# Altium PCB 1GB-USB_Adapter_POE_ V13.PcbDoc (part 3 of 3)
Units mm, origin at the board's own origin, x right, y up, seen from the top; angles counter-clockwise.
Board outline 92 x 80 mm, 4 copper layers (Top Layer, Signal Layer 2, Signal Layer 3, Bottom Layer), stack 1.57 mm thick; 189 components, 102 nets, 551 pads, 429 vias.
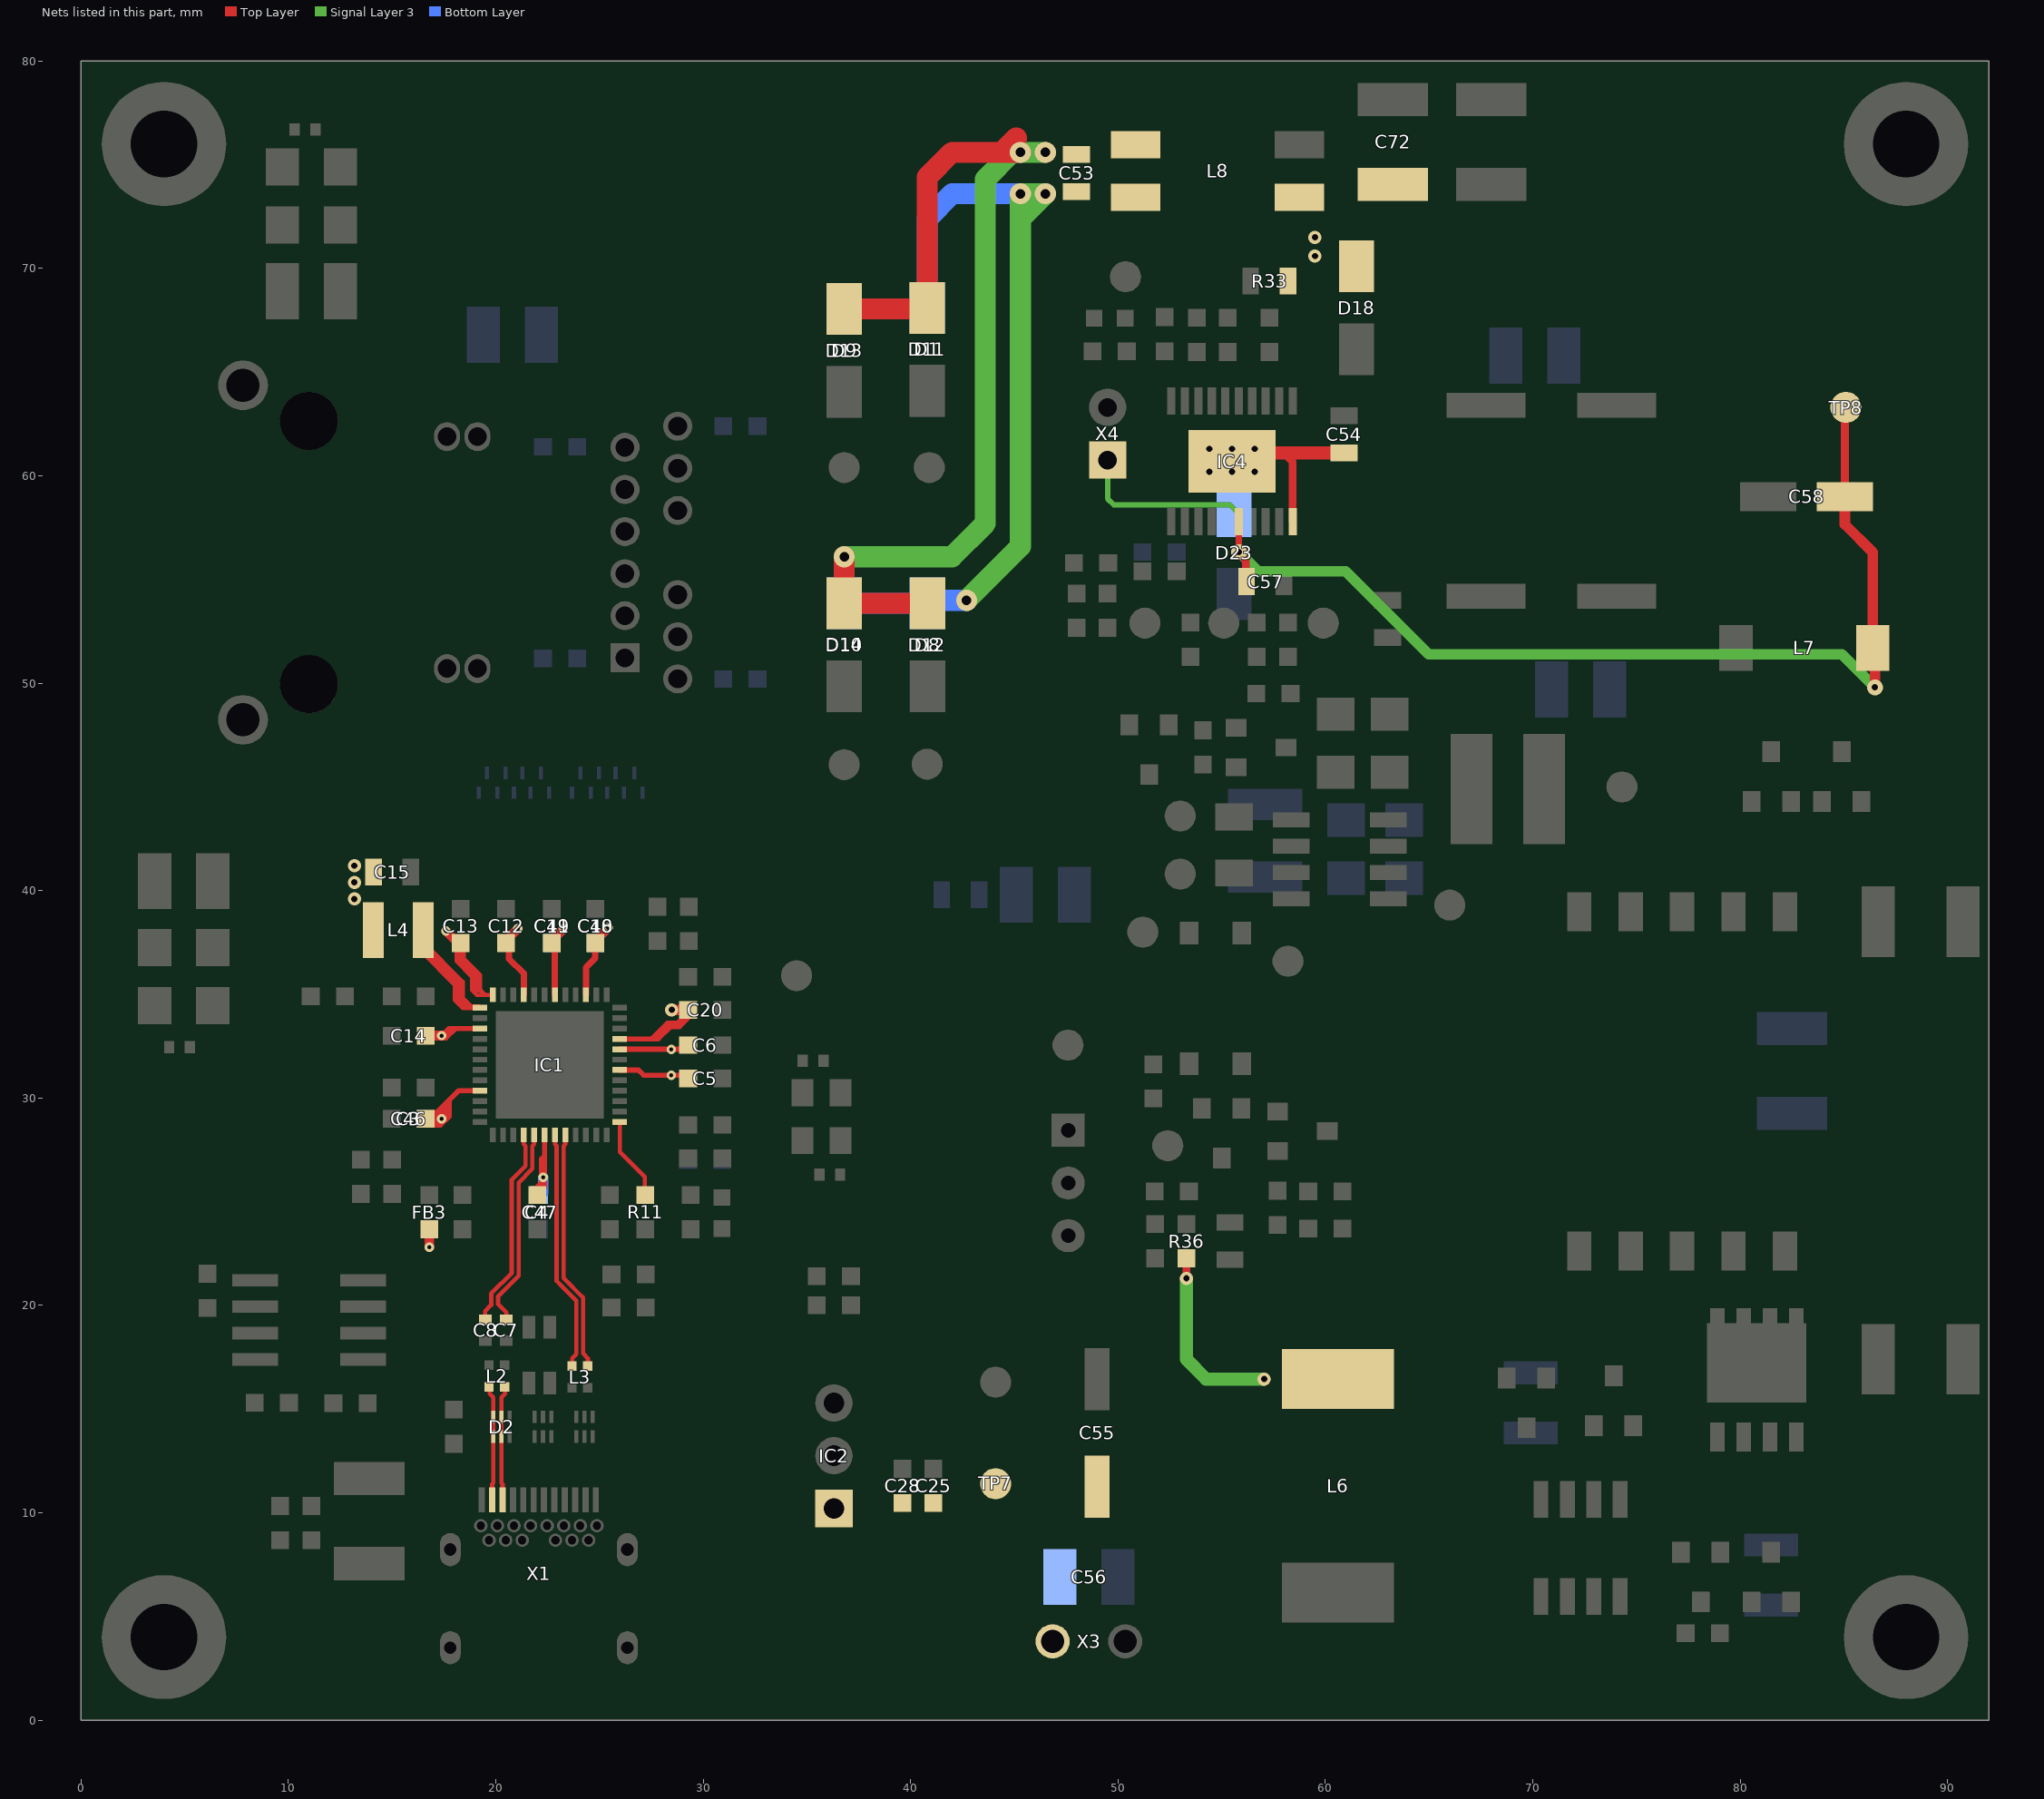
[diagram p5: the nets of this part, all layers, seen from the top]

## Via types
v1: diameter 0.635, hole 0.3, Top Layer to Bottom Layer, tented both sides, 260 vias
v2: diameter 0.45, hole 0.2, Top Layer to Bottom Layer, tented both sides, 80 vias
v3: diameter 1.016, hole 0.457, Top Layer to Bottom Layer, tented both sides, 55 vias
v4: diameter 1.016, hole 0.508, Top Layer to Bottom Layer, 32 vias
v5: diameter 0.762, hole 0.3, Top Layer to Bottom Layer, tented both sides, 2 vias

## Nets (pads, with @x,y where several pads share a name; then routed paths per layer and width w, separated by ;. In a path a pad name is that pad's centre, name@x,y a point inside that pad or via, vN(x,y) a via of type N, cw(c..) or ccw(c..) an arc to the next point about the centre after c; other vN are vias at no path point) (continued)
USB3RX_N: IC1.32 L3.3 | length 12.3
  Top Layer w0.206: IC1.32@23.35,28.225 23.35,27.772 23.266,27.689 23.266,21.314 23.48,21.1 ; L3.3@24.436,17.125 24.436,17.453 24.211,17.678 24.211,20.369 23.98,20.6 ; 23.48,21.1 23.98,20.6 ; 23.48,21.1 23.98,20.6
USB3RX_P: IC1.31 L3.2 | length 12.3
  Top Layer w0.206: IC1.31@22.85,28.225 22.85,27.772 22.934,27.688 22.934,21.176 23.147,20.962 ; L3.2@23.686,17.125 23.686,17.453 23.878,17.645 23.878,20.232 23.647,20.462 ; 23.147,20.962 23.647,20.462 ; 23.147,20.962 23.647,20.462
USB3TX1_N: D2.2 D2.5 L2.4 X1.A3 | length 5.5
  Top Layer w0.206: X1.A3@20.325,10.68 20.325,11.383 20.275,11.433 20.275,13.725 20.275,14.675 20.275,15.572 20.45,15.747 L2.4@20.45,16.075
USB3TX1_P: D2.1 D2.6 L2.1 X1.A2 | length 5.5
  Top Layer w0.206: L2.1@19.7,16.075 19.7,15.747 19.875,15.572 19.875,14.675 19.875,13.725 19.875,11.433 19.825,11.383 X1.A2@19.825,10.68
USB3TX_N: C7.2 IC1.29 | length 9.8
  Top Layer w0.206: C7.2@20.51,19.3 20.51,19.653 20.11,20.053 20.11,20.436 21.1,21.426 21.1,25.92 21.766,26.586 21.766,27.689 21.85,27.772 IC1.29@21.85,28.225
USB3TX_P: C8.2 IC1.28 | length 9.8
  Top Layer w0.206: C8.2@19.48,19.3 19.48,19.723 19.777,20.02 19.777,20.574 20.767,21.564 20.767,26.058 21.434,26.724 21.434,27.689 21.35,27.772 IC1.28@21.35,28.225
USBRBIAS: IC1.37 R11.1 | length 4
  Top Layer w0.203: IC1.37@25.975,28.85 25.975,27.405 27.18,26.2 R11.1@27.18,25.325
VC: C57.1 C58.1 IC4.6 L7.1 TP8.1 X4.1 | length 60.7
  Top Layer w0.305: IC4.6@55.825,57.8 v5(55.83,56.327)
  Top Layer w0.381: v5(55.83,56.327) 56.16,55.895 C57.1@56.16,54.879 ; C58.1@85.05,59 TP8.1@85.05,63.25
  Top Layer w0.508: C58.1@85.05,59 85.05,57.658 86.4,56.308 L7.1@86.4,51.7 ; v5(86.5,49.8) L7.1@86.5,51.6
  Signal Layer 3 w0.254: X4.1@49.5,60.76 49.5,58.9 49.8,58.6 55.4,58.6 55.83,58.17 v5(55.83,56.327)
  Signal Layer 3 w0.508: v5(55.83,56.327) 56.757,55.4 60.977,55.4 64.977,51.4 84.9,51.4 v5(86.5,49.8)
VDD12: C3.1 C4.1 C5.1 C6.1 C14.1 C15.2 C46.1 C47.1 FB3.2 IC1.15 IC1.21 IC1.30 IC1.42 IC1.44 L4.2 | length 24.9
  Top Layer w0.25: C14.1@16.586,33.005 16.713,33.132 17.538,33.132 17.756,33.35 18.046,33.35 ; C3.1@16.606,29 16.906,28.7 17.332,28.7 17.756,29.124 17.756,29.45 17.756,29.9 ; C14.1@16.691,32.9 17.386,32.9 17.596,32.9 18.046,33.35 ; C3.1@16.713,29.3 17.156,29.3 17.443,29.587 17.756,29.9 ; IC1.21@19.225,30.35 18.206,30.35 17.756,29.9 ; IC1.15@19.225,33.35 18.046,33.35 ; IC1.30@22.35,28.225 22.35,27.197 ; IC1.42@25.975,31.35 26.88,31.35 27.13,31.1 28.955,31.1 v2(28.46,31.1) ; IC1.44@25.975,32.35 C6.1@29.205,32.35 ; 22.35,27.197 22.35,26.172 22.35,25.695 21.98,25.325 21.98,25.68 22.2,25.9 22.2,26.172 22.2,27.047 22.35,27.197
  Top Layer w0.45: v2(16.8,22.8) FB3.2@16.8,23.674
  Top Layer w0.508: C3.1@16.606,29 17.13,29 17.293,29.163 17.58,29.45
  Bottom Layer w0.5: C47.1@22.28,25.425 v2(22.28,26.172)
  Bottom Layer w0.508: C46.1@16.605,29 v2(17.38,29)
  other v1: 13.18,39.6 13.18,40.4 13.18,41.2
  other v2: 28.46,32.345 17.386,33.005
VDD12_SW_OUT: IC1.13 L4.1 | length 13.7
  Top Layer w0.25: L4.1@16.452,38.085 L4.1@16.452,37.523 ; IC1.13@19.18,34.4 18.8,34.4 18.38,34.82 18.38,35.595 L4.1@16.452,37.523 ; IC1.13@19.225,34.35 18.8,34.35 18.58,34.35 ; L4.1@16.452,37.328 L4.1@16.452,37.523 ; L4.1@16.452,37.328 16.452,37.064 18.046,35.47 18.046,34.734 18.105,34.675 18.43,34.35 18.58,34.35 ; L4.1@16.452,37.328 18.18,35.6 18.18,34.75 18.505,34.425 18.58,34.35
VDD25: C10.1 C11.1 C12.1 C13.1 C20.1 C48.1 C49.1 IC1.3 IC1.6 IC1.9 IC1.12 IC1.45 | length 29.7
  Top Layer w0.2: C13.1@18.1,37.369 18.1,36.595 18.85,35.845 18.85,35.205 19.08,34.975 19.48,34.975 ; C13.1@18.175,37.369 C13.1@18.28,37.474 ; C13.1@18.45,37.304 18.45,36.73 19.25,35.93 19.25,35.205 19.48,34.975 ; IC1.12@19.85,34.975 19.48,34.975
  Top Layer w0.25: C13.1@18.28,37.474 18.28,37.369 18.28,36.64 19.032,35.888 19.032,35.3 19.127,35.205 19.25,35.205 ; IC1.45@25.975,32.85 27.53,32.85 ; v1(28.48,34.25) v1@28.505,34.225 ; v1@28.779,34.224 28.805,34.25 ; C20.1@29.279,34.25 29.279,34.116 28.763,33.6 28.28,33.6 27.53,32.85 ; C20.1@29.354,33.949 28.855,33.45 28.43,33.45 27.83,32.85 27.53,32.85
  Top Layer w0.305: C12.1@20.48,37.474 20.637,37.318 20.637,36.713 21.35,36 IC1.9@21.35,34.975 ; C11.1@22.68,37.474 22.85,37.305 IC1.6@22.85,34.975 ; IC1.3@24.35,34.975 24.35,36.3 24.78,36.73 C10.1@24.78,37.474
  Top Layer w0.45: v2(17.593,38.056) C13.1@18.175,37.474 ; C13.1@18.28,37.474 C13.1@18.45,37.304 ; C12.1@20.48,37.58 v2(21.062,38.162) ; C11.1@22.68,37.58 v2(23.262,38.162) ; C10.1@24.83,37.63 v2(25.412,38.212)
  Top Layer w0.508: v1(28.48,34.25) 28.805,34.25 29.255,34.25 C20.1@29.279,34.25
  Bottom Layer w0.45: C49.1@22.68,37.58 v2(23.262,38.162) ; C48.1@24.78,37.58 v2(25.412,38.212)
VDD_POE: C53.2 D1.2 D8.2 D9.2 D10.2 L8.2 | length 50.1
  Top Layer w1.016: D10.2@36.8,53.85 D8.2@40.82,53.85 D8.2@40.9,53.93 ; D10.2@36.8,53.93 v3(36.8,56.1) ; D9.2@36.8,68.05 40.75,68.05 D1.2@40.8,68.1 40.8,74.4 42,75.6 44.4,75.6 ; 45.1,76.3 44.4,75.6 ; v3(45.3,75.6) 44.4,75.6
  Signal Layer 3 w1.016: v3(36.8,56.1) 42,56.1 43.6,57.7 43.6,74.3 44.9,75.6 v3(45.3,75.6) v3(46.5,75.6)
VOUT: C25.2 C28.1 C55.1 C56.1 IC2.1 L6.2 R36.2 TP7.1 X3.1 | length 9
  Top Layer w0.381: v1(53.3,21.3) R36.2@53.3,22.274
  Signal Layer 3 w0.635: v1(53.3,21.3) 53.3,17.4 54.25,16.45 v1(57.049,16.45)
VSS: C54.2 C72.2 D18.1 D23.1 IC4.10 IC4.21 L8.4 R33.1 | length 8.5
  Top Layer w0.381: 58,61.1 58.425,60.675 IC4.10@58.425,57.8
  Top Layer w0.635: IC4.21@55.9,61.1 58,61.1 C54.2@60.9,61.1
  other v1: 54.4,60.2 55.5,60.2 56.6,60.2 54.4,61.3 55.5,61.3 56.6,61.3 59.5,70.6 59.5,71.5
VSS_POE: C53.1 D11.1 D12.1 D13.1 D14.1 L8.1 | length 44.1
  Signal Layer 3 w1.016: v3(42.7,54) 45.3,56.6 45.3,72.4 ; 45.3,72.4 v3(46.5,73.6) v3(45.3,73.6) 45.3,72.4
  Bottom Layer w1.016: D14.1@36.8,53.85 D12.1@40.8,53.85 40.95,54 v3(42.7,54) ; D13.1@36.8,68.05 40.75,68.05 D11.1@40.8,68.1 40.8,72.4 42,73.6 v3(45.3,73.6) v3(46.5,73.6)
pads on no net: D2.4 D3.4 D4.4 D6.2 D6.4 D6.7 D6.8 D7.2 D7.4 D7.7 D7.8 D15.2 D16.2 D17.2 D19.2 D20.2 D21.2 D22.2 IC3.7 IC4.14 IC4.17 T2.3 T2.8 X1.A4 X1.A8 X1.A9 X1.A10 X1.A11 X1.B2 X1.B3 X1.B4 X1.B5 X1.B8 X1.B9 X2.MH1 X2.MH2

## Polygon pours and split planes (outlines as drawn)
AGND on Top Layer "NONET_L03_P-001" (solid, remove dead copper, pour order 58): 65.2,32.5 61.7,36 46.6,36 45.5,37.1 45.5,44.6 45.5,76.7 79.4,76.7 88.5,67.6 88.5,33.2 87.8,32.5
GND on Top Layer "NONET_L03_P-001" (solid, remove dead copper, pour order 56): 42.409,43.091 42.9,42.6 42.9,35.8 45.25,33.45 60.15,33.45 63.6,30 87.8,30 88.5,29.3 88.5,10.15 86.375,8.025 86.325,8.025 84,5.65 84,3.1 83.2,2.3 80.6,2.3 43.8,2.3 41.1,5 30,5 29.5,5.5 29.5,9.5 29,10 7,10 5,12 5,32.694 5.497,33.191 5.497,41.308 11.8,47.61 11.8,74 11.8,75.5 10.95,76.35 10.95,77.1 21.8,77.1 22.1,76.8 22.1,48.4 22.71,47.79 32.71,47.79 33.169,47.331 33.169,43.612 33.69,43.091
NetD17_3 on Top Layer "NONET_L-01_P-001" (solid, remove dead copper, pour order 36): 71.45,23.7 71.45,15.65 71.8,15.3 84.3,15.3 84.6,15.6 84.6,19.8 84.3,20.1 75.9,20.1 75.6,20.4 75.6,23.7 75.425,23.874 71.625,23.874
VOUT on Top Layer "NONET_L-01_P-001" (solid, remove dead copper, pour order 34): 45.515,2.9 45.2,3.215 45.2,8.1 44.821,8.479 35.02,8.479 34.67,8.829 34.67,10.99 35.013,11.333 42.133,11.333 44.3,13.5 51.6,13.5 56.65,18.55 64.05,18.55 64.3,18.3 64.3,14.284 64,13.984 56.759,13.984 48.4,5.625 48.4,3.1 48.2,2.9
NetC2_2 on Top Layer "NONET_L-01_P-001" (solid, remove dead copper, pour order 28): 59.55,46.7 59.4,46.55 59.4,44.716 59.516,44.6 61.75,44.6 61.95,44.4 61.95,38 62.05,37.9 66.846,37.9 67.1,38.154 67.1,40.081 66.993,40.188 64.6,40.188 64.3,40.488 64.3,46.5 64.1,46.7
NetR34_2 on Top Layer "Top Layer, Top-RCS" (solid, remove dead copper, pour order 26): 59.507,40.4 57.378,40.4 56.7,39.722 52.103,39.722 51.95,39.875 51.95,41.85 52.134,42.034 56.966,42.034 57.125,42.192 57.125,43.989 59.516,43.989 59.528,43.976
NetC45_1 on Top Layer "NONET_L-01_P-001" (solid, remove dead copper, pour order 22): 73.2,37.9 73.2,51.4 72.9,51.7 70,51.7 69.4,51.1 69.4,38.2 69.7,37.9
VSS on Top Layer "NONET_L-01_P-001" (solid, remove dead copper, pour order 16): 56.21,73.2 56.209,74.415 56.615,74.82 61.12,74.82 65.28,74.82 65.6,74.5 65.6,69.759 63.941,68.1 60.395,68.1 60.195,68.3 57.4,68.3 57.2,68.5 57.2,70.17 57.07,70.3 56.3,70.3 56.21,70.391
NetC34_1 on Top Layer "NONET_L-01_P-001" (solid, remove dead copper, pour order 14): 65.3,68.7 66.1,69.5 66.1,74.9 65.644,75.356 56.907,75.356 56.907,76.7 69.5,76.7 70.1,76.1 70.1,53.5 68.1,51.5 68.1,41.8 67.9,41.6 65.7,41.6 65.3,42 65.3,52.7 64.9,53.1 62.325,53.1 62.075,53.35 62.075,61.875 61.95,62 59.81,62 59.65,62.16 59.65,67.651 64.251,67.651
SHIELD on Top Layer "NONET_L-01_P-001" (solid, remove dead copper, pour order 10): 17.555,9.1 18.54,8.115 18.54,6.594 18.775,6.359 25.313,6.359 25.61,6.656 25.61,8.235 26.475,9.1 27.651,9.1 28.076,8.675 28.076,4.007 28.589,3.574 40.526,3.574 42.7,1.4 42.7,0 0,0 0,80 92,80 92,0 84.4,0 84.4,1.5 90,7.1 90,68.86 80.66,78.2 11.5,78.2 10.54,77.24 10.54,48.151 4.4,42.011 4.4,11.31 6.61,9.1
3V3_Board on Top Layer "NONET_L-01_P-001" (solid, remove dead copper, pour order 8): 33.1,14.5 33.4,14.2 37.734,14.2 37.979,14.445 37.979,18.646 37.675,18.95 36.354,18.95 36.104,19.2 36.104,21.969 35.973,22.1 33.3,22.1 33.1,21.9
GND on Top Layer "GND_OSC" (solid, remove dead copper, pour order 6): 33.303,32.525 33.603,32.825 38.003,32.825 38.303,32.525 38.303,25.655 37.979,25.331 33.548,25.331 33.303,25.575
3V3_Board on Top Layer "3V3_BOARD_L01_P004" (hatched Horizontal grid 0.203 track 0.203, remove dead copper, pour order 4): 28.445,36.08 29.025,36.08 29.025,35.62 28.955,35.55 28.63,35.55 27.78,34.7 27.78,33.7 27.43,33.35 26.763,33.35 27.28,33.867 27.28,34.915
3V3_Board on Top Layer "3V3_BOARD_L01_P002" (hatched Horizontal grid 0.203 track 0.203, remove dead copper, pour order 2): 28.28,29 27.43,29.85 27.08,29.85 27.525,29.405 27.525,28.555 27.68,28.4 28.955,28.4 29.217,28.662 29.217,29
3V3_Board on Top Layer "3V3_BOARD_L01_P000" (hatched Horizontal grid 0.203 track 0.203, remove dead copper, pour order 0): 27.68,27.4 28.955,27.4 28.955,26.8 27.48,26.8 26.856,27.424 26.856,28 27.08,28
GND on Bottom Layer "NONET_L03_P-001" (solid, remove dead copper, pour order 72): 42.9,41.275 42.725,41.1 42,41.1 41.75,40.85 41.75,38.85 42,38.6 42.7,38.6 42.9,38.4 42.9,36.804 42.9,35.8 45.25,33.45 60.15,33.45 63.6,30 87.8,30 88.5,29.3 88.5,10.15 86.375,8.025 86.325,8.025 84,5.65 84,3.1 83.2,2.3 80.6,2.3 43.8,2.3 41.1,5 30,5 29.5,5.5 29.5,9.5 29,10 7,10 5.497,11.503 5.497,33.191 5.497,41.308 11.804,47.614 11.804,63.404 12.239,63.839 21.661,63.839 22.1,63.4 22.1,48.4 22.71,47.79 32.71,47.79 33.169,47.331 33.169,43.612 33.69,43.091 42.41,43.091 42.9,42.6
AGND on Bottom Layer "NONET_L03_P-001" (solid, remove dead copper, pour order 64): 45.497,54.9 46.5,55.903 46.5,71.6 48,73.1 48,75.175 48.625,75.8 80.297,75.8 88.497,67.6 88.497,33.2 87.797,32.5 65.197,32.5 61.697,36 47.3,36 46.546,36.754 46.546,41.8 46.246,42.1 45.497,42.849 45.497,43.003 45.497,44.6
SHIELD on Bottom Layer "NONET_L-01_P-001" (solid, remove dead copper, pour order 48): 10.5,64.2 11.3,65 19.854,65 20.454,65.6 20.454,77.454 21.2,78.2 80.66,78.2 90,68.86 90,7.1 84.4,1.5 84.4,0 92,0 92,80 0,80 0,0 42.7,0 42.7,1.4 40.526,3.574 28.589,3.574 28.076,4.007 28.076,8.675 27.651,9.1 26.475,9.1 25.61,8.235 25.61,6.656 25.313,6.359 18.775,6.359 18.54,6.594 18.54,8.115 17.555,9.1 6.61,9.1 4.4,11.31 4.4,42.011 10.5,48.111
NetD17_3 on Bottom Layer "NONET_L-01_P-001" (solid, remove dead copper, pour order 38): 68.575,15.3 68.275,15.6 68.275,19.875 68.5,20.1 71.225,20.1 71.45,20.4 71.45,23.7 71.625,23.874 75.425,23.874 75.6,23.7 75.6,20.4 75.9,20.1 84.3,20.1 84.6,19.8 84.6,15.6 84.3,15.3
NetC45_1 on Bottom Layer "NONET_L-01_P-001" (solid, remove dead copper, pour order 24): 73.2,37.9 73.2,51.4 72.9,51.7 70,51.7 69.4,51.1 69.4,38.2 69.7,37.9
VSS on Bottom Layer "Bottom Layer, Bottom-VSS" (solid, remove dead copper, pour order 18): 60.222,71.878 60.1,72 57.7,72 57.555,71.855 57.555,64.586 57.461,64.492 53.631,64.492 53.618,64.479 53.618,57.621 53.631,57.608 60.221,57.608 60.374,57.765 60.222,68.556
GND on Signal Layer 2 "NONET_L03_P-001" (solid, remove dead copper, pour order 66): 42.9,37.167 42.9,35.8 45.275,33.48 45.31,33.45 60.15,33.45 63.6,30 87.8,30 88.5,29.3 88.5,10.15 86.375,8.025 86.325,8.025 84,5.65 84,3.1 83.2,2.3 80.6,2.3 43.8,2.3 41.1,5 30,5 29.5,5.5 29.5,9.5 29,10 26.865,10 24.565,7.7 19.643,7.7 17.343,10 15.88,10 7,10 5.497,11.503 5.497,33.191 5.497,41.308 11.8,47.61 11.8,72.7 11.8,76.796 12.104,77.1 21.8,77.1 22.1,76.8 22.1,48.4 22.71,47.79 32.71,47.79 33.169,47.331 33.169,43.612 33.69,43.091 42.409,43.091 42.9,42.6
AGND on Signal Layer 2 "NONET_L03_P-001" (solid, remove dead copper, pour order 60): 45.5,54.9 46.5,55.9 46.5,71.6 48,73.1 48,75.175 48.625,75.8 80.3,75.8 88.5,67.6 88.5,33.2 87.8,32.5 65.2,32.5 61.7,36 46.6,36 45.5,37.1 45.5,44.6
SHIELD on Signal Layer 2 "NONET_L-01_P-001" (solid, remove dead copper, pour order 44): 28.076,8.689 27.7,9.065 27.395,9.065 25.23,6.9 18.9,6.9 16.7,9.1 6.61,9.1 4.4,11.31 4.4,42.011 10.54,48.151 10.54,77.24 11.5,78.2 80.66,78.2 90,68.86 90,7.1 84.4,1.5 84.4,0 92,0 92,80 0,80 0,0 42.7,0 42.7,1.4 40.526,3.574 28.589,3.574 28.076,4.007
NetC52_2 on Signal Layer 2 "NONET_L03_P-001" (solid, remove dead copper, pour order 40): 57,6.9 57.2,7.1 80.825,7.1 85,11.275 85,24.8 85.1,24.9 87.6,24.9 87.7,24.8 87.7,9.9 83.2,5.4 83.2,3.495 82.505,2.8 57.23,2.8 57,3.03
GND on Signal Layer 3 "NONET_L03_P-001" (solid, remove dead copper, pour order 70): 42.9,36.965 42.9,35.798 45.248,33.45 46.05,33.45 60.15,33.45 63.6,30 87.8,30 88.5,29.3 88.5,10.15 86.375,8.025 86.325,8.025 84,5.65 84,3.1 83.2,2.3 80.6,2.3 43.8,2.3 41.1,5 30,5 29.5,5.5 29.5,9.5 29,10 7,10 5.497,11.503 5.497,33.191 5.497,41.308 11.804,47.614 11.804,76.8 12.104,77.1 13,77.1 21.8,77.1 22.1,76.8 22.1,48.4 22.71,47.79 32.71,47.79 33.169,47.331 33.169,43.612 33.69,43.091 42.409,43.091 42.9,42.6
AGND on Signal Layer 3 "NONET_L03_P-001" (solid, remove dead copper, pour order 62): 45.5,54.9 46.5,55.9 46.5,71.6 48,73.1 48,75.175 48.625,75.8 80.3,75.8 88.5,67.6 88.5,33.2 87.8,32.5 65.2,32.5 61.7,36 46.6,36 45.5,37.1 45.5,44.6
VDD12 on Signal Layer 3 "VDD12_L03_P054" (solid, remove dead copper, pour order 54): 16.446,35.139 16.446,32.7 16.573,32.573 17.97,32.573 18.097,32.446 18.097,29.601 17.894,29.398 15.766,29.398 15.608,29.256 15.608,22.489 15.785,22.312 16.979,22.312 17.132,22.464 17.132,25.537 17.259,25.664 28.562,25.664 28.714,25.817 28.714,32.522 28.587,32.649 26.901,32.649 26.784,32.767 26.784,36.459 26.53,36.713 17.309,36.713 17.055,36.967 17.055,42.507 16.855,42.708 12.585,42.708 12.382,42.505 12.382,35.596 12.56,35.418 16.166,35.418
3V3_Board on Signal Layer 3 "3V3_BOARD_L03_P052" (solid, remove dead copper, pour order 52): 31.051,22.349 31.4,22 34.6,22 34.8,21.8 34.8,20.2 34.581,19.981 23.719,19.981 23.5,20.2 23.507,22.921 23.355,23.074 19.265,23.074 19.164,22.972 19.164,20.534 18.935,20.305 11.196,20.305 10.9,19.981 10.9,15.872 10.728,15.7 8,15.7 7.8,15.9 7.8,34.508 8.1,34.808 15.992,34.808 16.18,34.62 16.18,32.433 16.293,32.319 17.741,32.319 17.868,32.192 17.868,29.83 17.716,29.678 15.506,29.678 15.328,29.5 15.328,22.286 15.531,22.083 17.233,22.083 17.462,22.312 17.462,25.106 17.741,25.385 28.778,25.385 28.943,25.549 28.943,32.7 28.765,32.878 27.038,32.878 26.936,32.98 26.936,34.605 27.139,34.808 27.825,34.808 27.952,34.681 27.952,33.767 28.028,33.691 30.898,33.691 31.051,33.538
VDD25 on Signal Layer 3 "VDD25_L03_P050" (solid, remove dead copper, pour order 50): 17.365,37.217 17.356,38.919 17.462,39.025 28.892,39.025 29.095,38.822 29.095,33.97 29.019,33.894 28.206,33.894 28.13,33.97 28.13,36.866 27.927,37.069 17.513,37.069
SHIELD on Signal Layer 3 "NONET_L-01_P-001" (solid, remove dead copper, pour order 46): 17.555,9.1 18.54,8.115 18.54,6.594 18.775,6.359 25.313,6.359 25.61,6.656 25.61,8.235 26.475,9.1 27.651,9.1 28.076,8.675 28.076,4.007 28.589,3.574 40.526,3.574 42.7,1.4 42.7,0 0,0 0,80 92,80 92,0 84.4,0 84.4,1.5 90,7.1 90,68.86 80.66,78.2 11.5,78.2 10.5,77.2 10.5,48.111 4.4,42.011 4.4,11.31 6.61,9.1
NetC52_2 on Signal Layer 3 "NONET_L03_P-001" (solid, remove dead copper, pour order 42): 57,6.9 57.2,7.1 80.5,7.1 85,11.6 85,24.8 85.1,24.9 87.6,24.9 87.7,24.8 87.7,10.2 83.2,5.7 83.2,3.495 82.505,2.8 57.23,2.8 57,3.03

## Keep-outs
Keep-Out Layer:
  the board outline again, w0.254

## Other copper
Top Layer:
  rectangle net VDD_POE: 44.7,75.066 52.095,76.9
  rectangle net SHIELD: 90.1,35.725 91.5,41.05
  rectangle net SHIELD: 90.1,14.625 91.5,19.95
  rectangle net VSS_POE: 44.7,72.5 52.1,74.146
  rectangle net NetC52_2: 78.895,21.3 87.7,24.9
  rectangle net NetC52_1: 78.4,7.5 82.2,9.6
  rectangle net NetC52_2: 76,3.5 78.14,6.4
  rectangle net NetC52_2: 69.9,3.3 74.7,7.1
  rectangle net NetC52_2: 57.5,2.901 63.7,8
  rectangle net VSS: 57.046,59.2 58.7,62.2
  rectangle net SHIELD: 40.4,0.4 85.1,1.6
  region net GND: 35.546,32.55 35.546,31.25 36.8,31.25 36.8,32.55
  region net GND: 35.92,31.435 35.92,29.189 37.6,29.189 37.6,31.435
  region net GND: 35.7,26.519 35.7,28.5 33.825,28.5 33.825,26.519
  region net GND: 35.854,25.55 35.854,26.85 34.6,26.85 34.6,25.55
  region net VDD12: 12.58,41.7 12.58,36.595 14.48,36.595 14.48,41.7
  pour cut-out: 45.5,72.293 52.164,72.293 52.291,72.421 52.291,76.791 52.4,76.9 56.907,76.9 56.907,71.536 56.764,71.393 45.5,71.393
  pour cut-out: 33.28,29.95 33.28,32.45 33.63,32.8 38.03,32.8 38.33,32.5 38.33,25.63 38.005,25.306 33.574,25.306 33.28,25.6 33.28,29.505 33.057,29.505 33.057,25.462 33.438,25.081 38.137,25.081 38.544,25.487 38.544,32.625 38.163,33.006 33.438,33.006 33.057,32.625 33.057,29.95
  text "Top Layer" at 35.8,92.826 h1.8
Signal Layer 2:
  rectangle net SHIELD: 40.4,0.4 85.1,1.6
  text "Inner Layer2 (GND Plane)" at 22.8,92.826 h1.8
Signal Layer 3:
  rectangle net SHIELD: 40.4,0.4 85.1,1.6
  pour cut-out: 26.075,4.248 18.275,4.248 18.275,9.708 18.238,9.745 26.075,9.745
  text "Inner Layer3 (Power/GND Plane)" at 22.8,93.126 h1.8
Bottom Layer:
  rectangle net SHIELD: 40.4,0.4 85.1,1.6
  rectangle net NetC52_1: 80.1,7.5 82.925,9.6
  rectangle net NetC52_1: 78.4,8.775 82.925,9.6
  rectangle net NetC52_2: 76,3.5 78.6,6.4
  rectangle net VOUT: 45.4,2.8 48.3,8.643
  rectangle net NetC34_1: 66.054,64.1 69.7,67.3
  rectangle net GND: 20.18,43.141 21.58,44.036
  rectangle net GND: 24.68,43.141 26.08,44.036
  pour cut-out: 26.075,4.248 18.275,4.248 18.275,9.708 18.238,9.745 26.075,9.745
  text "Bottom Layer" at 51,92.826 h1.8

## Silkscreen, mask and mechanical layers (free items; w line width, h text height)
Top Overlay:
  lines w1: 44.2,79.9 44.2,36.532 45.939,34.793 60.807,34.793 64.43,31.17 92,31.17
  text "1GB-USB Adapter with POE V1.3" at 15.1,74.8 h2
  text "Würth Elektronik" at 29.2,72.654 h1.8
  text "VOUT" at 39,3.241 h1.5
  text "+" at 43.223,0.7 h1.5
  text "-" at 53.3,0.5 h1.5
Bottom Overlay:
  lines w1: 44.2,37.697 44.2,36.532 45.939,34.793 60.807,34.793 64.43,31.17 92,31.17 ; 44.2,41.9 44.2,79.9
Mechanical 1:
  drawing of 295 lines, arcs and shapes, not listed
  text "Layer" at 108.243,90.146 h1.52
  text "Name" at 118.655,90.146 h1.52
  text "Material" at 142.524,90.146 h1.52
  text "Thickness" at 164.362,90.146 h1.52
  text "Constant" at 180.868,90.146 h1.52
  text "Board Layer Stack" at 195.342,90.146 h1.52
  text "1" at 108.243,87.098 h1.52
  text "Top Overlay" at 118.655,87.098 h1.52
  text "2" at 108.243,84.05 h1.52
  text "Top Solder" at 118.655,84.05 h1.52
  text "Solder Resist" at 142.524,84.05 h1.52
  text "0.010mm" at 164.362,84.05 h1.52
  text "3.8" at 180.868,84.05 h1.52
  text "3" at 108.243,81.002 h1.52
  text "Top Layer" at 118.655,81.002 h1.52
  text "Copper" at 142.524,81.002 h1.52
  text "0.035mm" at 164.362,81.002 h1.52
  text "4" at 108.243,77.954 h1.52
  text "Dielectric 1" at 118.655,77.954 h1.52
  text "7628" at 142.524,77.954 h1.52
  text "0.200mm" at 164.362,77.954 h1.52
  text "4.6" at 180.868,77.954 h1.52
  text "5" at 108.243,74.906 h1.52
  text "Signal Layer 2" at 118.655,74.906 h1.52
  text "Copper" at 142.524,74.906 h1.52
  text "0.018mm" at 164.362,74.906 h1.52
  text "6" at 108.243,71.858 h1.52
  text "Dielectric 3" at 118.655,71.858 h1.52
  text "Core-009" at 142.524,71.858 h1.52
  text "1.065mm" at 164.362,71.858 h1.52
  text "4.6" at 180.868,71.858 h1.52
  text "7" at 108.243,68.81 h1.52
  text "Signal Layer 3" at 118.655,68.81 h1.52
  text "Copper" at 142.524,68.81 h1.52
  text "0.018mm" at 164.362,68.81 h1.52
  text "8" at 108.243,65.762 h1.52
  text "Dielectric 2" at 118.655,65.762 h1.52
  text "PP-006" at 142.524,65.762 h1.52
  text "0.200mm" at 164.362,65.762 h1.52
  text "4.6" at 180.868,65.762 h1.52
  text "9" at 108.243,62.714 h1.52
  text "Bottom Layer" at 118.655,62.714 h1.52
  text "Copper" at 142.524,62.714 h1.52
  text "0.035mm" at 164.362,62.714 h1.52
  text "10" at 108.243,59.666 h1.52
  text "Bottom Solder" at 118.655,59.666 h1.52
  text "Solder Resist" at 142.524,59.666 h1.52
  text "0.010mm" at 164.362,59.666 h1.52
  text "3.8" at 180.868,59.666 h1.52
  text "11" at 108.243,56.618 h1.52
  text "Bottom Overlay" at 118.655,56.618 h1.52
Drill Drawing:
  circle w0.254: c109.094,40.987 r0.847
  circle w0.254: c109.094,14.317 r0.508
  circle w0.254: c109.094,14.317 r0.847
  lines w0.254: 108.247,-1.77 109.941,-1.77 109.941,-0.077 108.247,-0.077 108.247,-1.77 ; 108.247,2.04 108.247,2.463 108.671,2.887 108.247,3.31 108.247,3.733 108.671,3.733 109.094,3.31 109.517,3.733 109.941,3.733 109.941,3.31 109.517,2.887 109.941,2.463 109.941,2.04 109.517,2.04 109.094,2.463 108.671,2.04 108.247,2.04 ; 108.247,6.697 109.094,5.85 109.941,6.697 109.094,7.543 108.247,6.697 ; 108.247,10.083 108.671,10.083 108.671,9.66 109.517,9.66 109.517,10.083 109.941,10.083 109.941,10.93 109.517,10.93 109.517,11.353 108.671,11.353 108.671,10.93 108.247,10.93 108.247,10.083 ; 108.247,18.973 109.941,18.973 109.094,17.28 108.247,18.973 ; 108.247,21.09 109.094,21.513 109.941,21.09 109.517,21.937 109.941,22.783 109.094,22.36 108.247,22.783 108.671,21.937 108.247,21.09 ; 108.247,25.323 108.671,25.323 109.094,24.9 109.517,25.323 109.941,25.323 109.517,25.747 109.941,26.17 109.517,26.17 109.094,26.593 108.671,26.17 108.247,26.17 108.671,25.747 108.247,25.323 ; 108.247,28.71 109.094,29.133 109.941,28.71 109.517,29.557 109.941,30.403 109.094,29.98 108.247,30.403 108.671,29.557 108.247,28.71 ; 108.247,32.943 108.671,32.943 109.094,32.52 109.517,32.943 109.941,32.943 109.517,33.367 109.941,33.79 109.517,33.79 109.094,34.213 108.671,33.79 108.247,33.79 108.671,33.367 108.247,32.943 ; 108.247,36.33 109.941,36.33 109.941,38.023 108.247,38.023 108.247,36.33 ; 108.247,45.643 109.941,45.643 109.094,43.95 108.247,45.643 ; 108.586,-1.431 109.602,-1.431 109.602,-0.415 108.586,-0.415 108.586,-1.431 ; 108.586,29.049 109.094,29.303 109.602,29.049 109.348,29.557 109.602,30.065 109.094,29.811 108.586,30.065 108.84,29.557 108.586,29.049 ; 108.586,33.113 108.84,33.113 109.094,32.859 109.348,33.113 109.602,33.113 109.348,33.367 109.602,33.621 109.348,33.621 109.094,33.875 108.84,33.621 108.586,33.621 108.84,33.367 108.586,33.113 ; 108.586,45.305 109.602,45.305 109.094,44.289 108.586,45.305
  lines w0.381: 106.729,-2.913 331.71,-2.913 ; 106.729,46.617 331.71,46.617 ; 120.721,-6.723 120.721,50.427 ; 135.703,-6.723 135.703,50.427 ; 164.905,-6.723 164.905,50.427 ; 177.754,-6.723 177.754,50.427 ; 196.392,-6.723 196.392,50.427 ; 234.481,-6.723 234.481,50.427 ; 249.463,-6.723 249.463,50.427 ; 268.406,-6.723 268.406,50.427 ; 296.084,-6.723 296.084,50.427 ; 106.729,-6.723 331.71,-6.723 331.71,50.427 106.729,50.427 106.729,-6.723
  text "Symbol" at 109.015,47.76 h1.83
  text "Count" at 121.864,47.76 h1.83
  text "Hole Size" at 136.846,47.76 h1.83
  text "Plated" at 166.048,47.76 h1.83
  text "Hole Type" at 178.897,47.76 h1.83
  text "Drill Layer Pair" at 197.535,47.76 h1.83
  text "Via/Pad" at 235.624,47.76 h1.83
  text "Pad Shape" at 250.606,47.76 h1.83
  text "Hole Length" at 269.549,47.76 h1.83
  text "Routed Path Length" at 297.227,47.76 h1.83
  text "2" at 121.864,43.95 h1.52
  text "1.100mm (43.31mil)" at 136.846,43.95 h1.52
  text "PTH" at 166.048,43.95 h1.52
  text "Round" at 178.897,43.95 h1.52
  text "Top Layer - Bottom Layer" at 197.535,43.95 h1.52
  text "Pad" at 235.624,43.95 h1.52
  text "Rounded" at 250.606,43.95 h1.52
  text "-" at 269.549,43.95 h1.52
  text "-" at 297.227,43.95 h1.52
  text "2" at 121.864,40.14 h1.52
  text "1.600mm (62.99mil)" at 136.846,40.14 h1.52
  text "PTH" at 166.048,40.14 h1.52
  text "Round" at 178.897,40.14 h1.52
  text "Top Layer - Bottom Layer" at 197.535,40.14 h1.52
  text "Pad" at 235.624,40.14 h1.52
  text "Rounded" at 250.606,40.14 h1.52
  text "-" at 269.549,40.14 h1.52
  text "-" at 297.227,40.14 h1.52
  text "2" at 121.864,36.33 h1.52
  text "2.800mm (110.24mil)" at 136.846,36.33 h1.52
  text "NPTH" at 166.048,36.33 h1.52
  text "Round" at 178.897,36.33 h1.52
  text "Top Layer - Bottom Layer" at 197.535,36.33 h1.52
  text "Pad" at 235.624,36.33 h1.52
  text "Rounded" at 250.606,36.33 h1.52
  text "-" at 269.549,36.33 h1.52
  text "-" at 297.227,36.33 h1.52
  text "3" at 121.864,32.52 h1.52
  text "0.700mm (27.56mil)" at 136.846,32.52 h1.52
  text "PTH" at 166.048,32.52 h1.52
  text "Round" at 178.897,32.52 h1.52
  text "Top Layer - Bottom Layer" at 197.535,32.52 h1.52
  text "Pad" at 235.624,32.52 h1.52
  text "(Mixed)" at 250.606,32.52 h1.52
  text "-" at 269.549,32.52 h1.52
  text "-" at 297.227,32.52 h1.52
  text "3" at 121.864,28.71 h1.52
  text "1.000mm (39.37mil)" at 136.846,28.71 h1.52
  text "PTH" at 166.048,28.71 h1.52
  text "Round" at 178.897,28.71 h1.52
  text "Top Layer - Bottom Layer" at 197.535,28.71 h1.52
  text "Pad" at 235.624,28.71 h1.52
  text "(Mixed)" at 250.606,28.71 h1.52
  text "-" at 269.549,28.71 h1.52
  text "-" at 297.227,28.71 h1.52
  text "4" at 121.864,24.9 h1.52
  text "0.600mm (23.62mil)" at 136.846,24.9 h1.52
  text "PTH" at 166.048,24.9 h1.52
  text "Slot" at 178.897,24.9 h1.52
  text "Top Layer - Bottom Layer" at 197.535,24.9 h1.52
  text "Pad" at 235.624,24.9 h1.52
  text "Rounded" at 250.606,24.9 h1.52
  text "1.200mm (47.24mil)" at 269.549,24.9 h1.52
  text "0.600mm (23.62mil)" at 297.227,24.9 h1.52
  text "4" at 121.864,21.09 h1.52
  text "3.200mm (125.98mil)" at 136.846,21.09 h1.52
  text "PTH" at 166.048,21.09 h1.52
  text "Round" at 178.897,21.09 h1.52
  text "Top Layer - Bottom Layer" at 197.535,21.09 h1.52
  text "Pad" at 235.624,21.09 h1.52
  text "Rounded" at 250.606,21.09 h1.52
  text "-" at 269.549,21.09 h1.52
  text "-" at 297.227,21.09 h1.52
  text "14" at 121.864,17.28 h1.52
  text "0.400mm (15.75mil)" at 136.846,17.28 h1.52
  text "PTH" at 166.048,17.28 h1.52
  text "Round" at 178.897,17.28 h1.52
  text "Top Layer - Bottom Layer" at 197.535,17.28 h1.52
  text "Pad" at 235.624,17.28 h1.52
  text "Rounded" at 250.606,17.28 h1.52
  text "-" at 269.549,17.28 h1.52
  text "-" at 297.227,17.28 h1.52
  text "18" at 121.864,13.47 h1.52
  text "0.900mm (35.43mil)" at 136.846,13.47 h1.52
  text "PTH" at 166.048,13.47 h1.52
  text "Round" at 178.897,13.47 h1.52
  text "Top Layer - Bottom Layer" at 197.535,13.47 h1.52
  text "Pad" at 235.624,13.47 h1.52
  text "(Mixed)" at 250.606,13.47 h1.52
  text "-" at 269.549,13.47 h1.52
  text "-" at 297.227,13.47 h1.52
  text "32" at 121.864,9.66 h1.52
  text "0.508mm (20.00mil)" at 136.846,9.66 h1.52
  text "PTH" at 166.048,9.66 h1.52
  text "Round" at 178.897,9.66 h1.52
  text "Top Layer - Bottom Layer" at 197.535,9.66 h1.52
  text "Via" at 235.624,9.66 h1.52
  text "Rounded" at 250.606,9.66 h1.52
  text "-" at 269.549,9.66 h1.52
  text "-" at 297.227,9.66 h1.52
  text "55" at 121.864,5.85 h1.52
  text "0.457mm (18.00mil)" at 136.846,5.85 h1.52
  text "PTH" at 166.048,5.85 h1.52
  text "Round" at 178.897,5.85 h1.52
  text "Top Layer - Bottom Layer" at 197.535,5.85 h1.52
  text "Via" at 235.624,5.85 h1.52
  text "Rounded" at 250.606,5.85 h1.52
  text "-" at 269.549,5.85 h1.52
  text "-" at 297.227,5.85 h1.52
  text "80" at 121.864,2.04 h1.52
  text "0.200mm (7.87mil)" at 136.846,2.04 h1.52
  text "PTH" at 166.048,2.04 h1.52
  text "Round" at 178.897,2.04 h1.52
  text "Top Layer - Bottom Layer" at 197.535,2.04 h1.52
  text "Via" at 235.624,2.04 h1.52
  text "Rounded" at 250.606,2.04 h1.52
  text "-" at 269.549,2.04 h1.52
  text "-" at 297.227,2.04 h1.52
  text "262" at 121.864,-1.77 h1.52
  text "0.300mm (11.81mil)" at 136.846,-1.77 h1.52
  text "PTH" at 166.048,-1.77 h1.52
  text "Round" at 178.897,-1.77 h1.52
  text "Top Layer - Bottom Layer" at 197.535,-1.77 h1.52
  text "Via" at 235.624,-1.77 h1.52
  text "Rounded" at 250.606,-1.77 h1.52
  text "-" at 269.549,-1.77 h1.52
  text "-" at 297.227,-1.77 h1.52
  text "481 Total" at 121.864,-5.58 h1.52
  text "Slot definitions :" at 109.015,-9.262 h1.52
  text "Routed Path Length" at 135.245,-9.262 h1.52
  text "= Calculated from tool start centre position to tool end centre position." at 163.253,-9.262 h1.52
  text "Hole Length" at 135.245,-11.802 h1.52
  text "= Routed Path Length + Tool Size = Slot length as defined in the PCB layout" at 152.842,-11.802 h1.52

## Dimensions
0,0 to 92,0 on Mechanical 1
0,80 to 0,0 on Mechanical 1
